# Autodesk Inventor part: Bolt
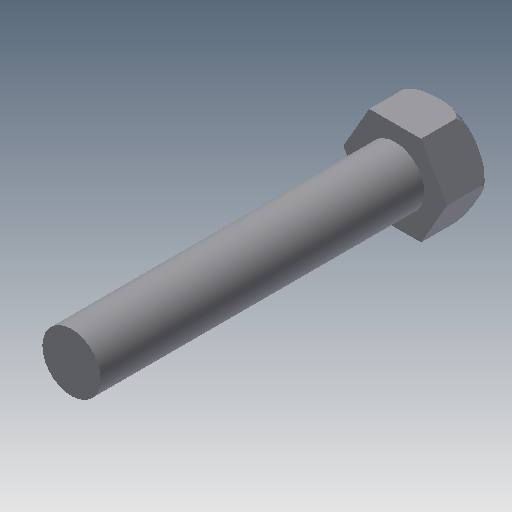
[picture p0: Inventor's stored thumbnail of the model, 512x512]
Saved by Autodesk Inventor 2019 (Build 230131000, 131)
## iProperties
Shininess: 77.0
Length Units: 11269
Angle Units: 11279
Time Units: 11290
Mass Units: 11283
Length Display Precision: 3
Angle Display Precision: 2
Created: 2002-02
Part Number: Bolt
Document SubType Name: Modeling
Designer: ***
Density: 1 g/cm^3
Material: Generic
Appearance: Default
Density: 0.0
Volumn: 0.0
Area: 0.0
PropertySet Name: Model Information
Control State: 0
Master: False
Checked Out: False
Author: ***
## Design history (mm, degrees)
sketch "Sketch1"
  geometry: C1 r 4 at (0, 0)
  constraints: 1 centre point
  dimensions: "d0" = 8 diameter of C1
extrude "Extrusion1" new body sketch "Sketch1" stored distance "d1" = 3.5; taper "d2" = 0 deg
fillet "Fillet1" dims "d3" = 1
sketch "Sketch2"
  geometry: L1 (4, 0)-(2, -3.464); L2 (2, -3.464)-(-2, -3.464); L3 (-2, -3.464)-(-4, 0); L4 (-4, 0)-(-2, 3.464); L5 (-2, 3.464)-(2, 3.464); L6 (2, 3.464)-(4, 0); 2 further points
  constraints: 12 end point, 1 coincident, 11 other
extrude "Extrusion2" sketch "Sketch2" extent not by distance; stored distance "d4" = 3.5; taper "d5" = 0 deg
sketch "Sketch3"
  geometry: C1 r 2.25 at (0, 0)
  constraints: 1 centre point
  dimensions: "d6" = 4.5 diameter of C1
extrude "Extrusion3" join sketch "Sketch3" distance "d7" = 25; taper "d8" = 0 deg
body "Solid1"
